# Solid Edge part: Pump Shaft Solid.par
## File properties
Title: Pump Shaft
Author: Dan
Comments: Rely Investment Cast Shrinkage  2.6%:  X 1.026 Measured Sizes.  EN 19   Die No 3669  Machine  Heat treat to Condition T  Grind  Nitride, Silver Grey Finish
Template: Pump Shaft.par
Last saved by: Dan
Revision: 14
Application: Solid Edge
Material: steel en19
Density: 7.85 kg/dm^3
Accuracy: 0.99
Document Number: P52-003
Project Name: Piston Pump P52
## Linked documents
Pump Shaft.par
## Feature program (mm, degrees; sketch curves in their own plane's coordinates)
part copy "CopiedPart_1"
sketch for "unnamed RevolvedProtrusion 1" #1 plane through (0, -50.8006, -62.7774) normal (1, 0, 0) x-axis (0, 1, 0)
  line (73.3006, 168.7774) -> (50.8006, 168.7774)
  line (68.8006, 105.7774) -> (50.8006, 105.7774)
  line (68.8006, 105.7774) -> (68.8006, 132.2774)
  line (68.8006, 132.2774) -> (67.2006, 132.2774)
  line (67.2006, 132.2774) -> (67.2006, 134.7774)
  line (68.8006, 134.7774) -> (67.2006, 134.7774)
  line (68.8006, 134.7774) -> (68.8006, 156.7774)
  line (73.3006, 156.7774) -> (68.8006, 156.7774)
  line (73.3006, 156.7774) -> (73.3006, 168.7774)
sketch for "unnamed RevolvedProtrusion 1" #2 plane through (0, -50.8006, -62.7774) normal (1, 0, 0) x-axis (0, 1, 0)
  line (50.8006, 252.2774) -> (64.0077, 252.2774)
  line (65.3006, 250.9845) -> (64.0077, 252.2774)
  line (65.3006, 222.2774) -> (65.3006, 250.9845)
  line (50.8006, 222.2774) -> (65.3006, 222.2774)
  line (50.8006, 252.2774) -> (50.8006, 222.2774)
revolve "unnamed RevolvedProtrusion 1" add full turn 360 deg about sketch line (50.8006, 168.7774) -> (50.8006, 105.7774)
sketch for "unnamed RevolvedProtrusion 2" plane through (0, -52.3376, -91.9458) normal (1, 0, 0) x-axis (0, 1, 0)
  line (73.1201, 240.4485) -> (74.3155, 240.814)
  line (80.7477, 219.7752) -> (74.3155, 240.814)
  line (59.2308, 213.1969) -> (80.7477, 219.7752)
  line (72.7075, 246.0736) -> (51.1906, 239.4953)
  line (73.5846, 243.2047) -> (72.7075, 246.0736)
  line (72.3892, 242.8392) -> (73.5846, 243.2047)
  line (73.1201, 240.4485) -> (72.3892, 242.8392)
revolve "unnamed RevolvedProtrusion 2" add full turn 360 deg about sketch line (51.1906, 239.4953) -> (59.2308, 213.1969)
sketch for "unnamed Protrusion 1" plane through (0, 0, 0) normal (0, 0, -1) x-axis (-1, 0, 0)
  line (-3, 15.7162) -> (-3, 17.7482)
  line (3, 17.7482) -> (3, 15.7162)
extrude "unnamed Protrusion 1" add to key point along -normal
pattern "unnamed Pattern 1" of "unnamed Protrusion 1"
extrude "unnamed Protrusion 2" add finite 40
extrude "unnamed Protrusion 3" add finite 40
extrude "unnamed Protrusion 4" add finite 40
extrude "unnamed Protrusion 5" add finite 40
extrude "unnamed Protrusion 6" add finite 40
extrude "unnamed Protrusion 7" add finite 40
extrude "unnamed Protrusion 8" add finite 40
sketch for "unnamed RevolvedCutout 1" plane through (0, 0, 0) normal (0, -1, 0) x-axis (1, 0, 0)
  line (15.5, 0) -> (22.0675, 6.5675)
revolve "unnamed RevolvedCutout 1" cut finite 360 deg
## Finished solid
Body 1: solid body, 100 faces, 241 edges, 146 vertices.
  Faces by surface: cylinder 45, plane 31, cone 19, torus 4, spline 1
  Edges by curve: circle 112, line 66, intersection 59, curve on surface 2, ellipse 2
Bounding box of the edges (mm; curved faces can reach further): 90.000 x 84.576 x 189.500, from (-45, -39.5763, 0) to (45.0001, 45, 189.5).
Cylindrical faces by radius (mm): R0.6 x1, R0.8 x16, R5 x1, R14.5 x1, R15 x1, R15.9 x8, R16.4 x1, R18 x10, R20 x1, R21.25 x1, R22.5 x3, R45 x1
Conical faces (half-angle, radius in mm at the cone's reference point): 17 deg R34.7934 x1, 45 deg R14.5 x1, 45 deg R19.1444 x16, 73 deg R43.3682 x1
Toroidal faces (ring radius, tube radius in mm): R17 r3 x1, R42.491 r3 x1, R44.4 r0.6 x2
Planar faces by outward normal: +x 2, +y 2, +z 3, -x 2, -y 2, -z 8, oblique 12
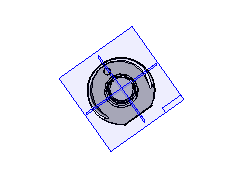
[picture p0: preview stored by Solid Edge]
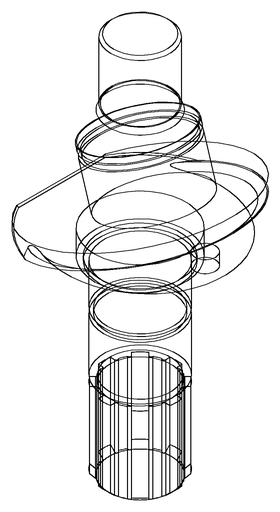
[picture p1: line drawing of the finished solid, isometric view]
